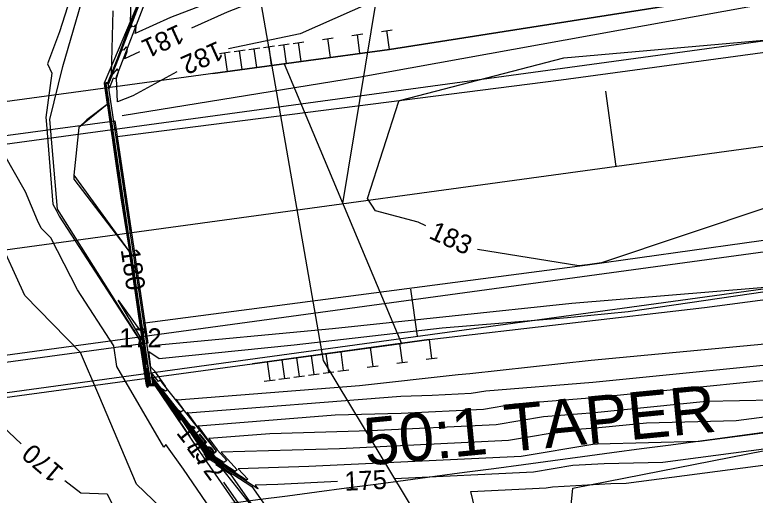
# Model space of a CAD drawing. Extents: x 2086416 to 2115205, y 575507 to 632762.
# Drawn here: x 2111556.7 to 2111634.6, y 581629.5 to 581680.1 of the extents above; entities that cross this region are included whole.
import ezdxf

# ---------------------------------------------------------------- set-up
doc = ezdxf.new("R2010")
doc.units = 0
for name, color, linetype in [('Default', 7, 'Continuous'), ('DTM Contours Major', 7, 'Continuous'), ('DTM Contours Major Text', 7, 'Continuous'), ('DTM Contours Minor', 7, 'Continuous'), ('DTM Contours Minor Text', 7, 'Continuous'), ('Exist Guardrail', 7, 'Continuous'), ('Exist Hydro Stream or Body of Water', 7, 'Continuous'), ('Exist Hydrographic Stream Bed', 7, 'Continuous'), ('Exist Right of Way Line', 7, 'Continuous'), ('Exist Roads EOP', 7, 'Continuous'), ('Exist Structure Major Bridge WW', 7, 'Continuous'), ('Exist Structure Major Deck Tunnel Box Culvert', 7, 'Continuous'), ('Exist Vegetation Woods Line', 7, 'Continuous'), ('Prop Horizontal Alignment', 7, 'Continuous'), ('Prop Horizontal Alignment Station Label', 7, 'Continuous'), ('Prop Horizontal Alignment Tick Large', 7, 'Continuous'), ('Prop Roadway Bridge', 7, 'Continuous'), ('Prop SS Cut Line', 7, 'Continuous')]:
    doc.layers.add(name, color=color, linetype=linetype)

msp = doc.modelspace()

# ---------------------------------------------------------------- linework, layer by layer
at = {"layer": 'Default'}
for p, q in [((2111430.061, 581649.328), (2112312.029, 581769.688)), ((2111433.036, 581627.53), (2112315.004, 581747.89)), ((2111508.232, 581633.802), (2112048.04, 581707.887)), ((2111629.262, 581649.262), (2111999.857, 581699.836)), ((2111629.262, 581649.262), (2111999.857, 581699.836)), ((2111596.112, 581676.446), (2111624.935, 581680.968)), ((2111624.935, 581680.968), (2111596.112, 581676.446)), ((2111595.274, 581678.35), (2111596.409, 581678.505)), ((2111596.112, 581676.446), (2111595.842, 581678.427)), ((2111589.081, 581677.505), (2111590.216, 581677.66)), ((2111592.178, 581677.927), (2111593.313, 581678.082)), ((2111593.016, 581676.023), (2111592.745, 581678.005)), ((2111584.437, 581676.871), (2111585.572, 581677.026)), ((2111585.275, 581674.967), (2111585.004, 581676.949)), ((2111585.985, 581677.082), (2111587.12, 581677.237)), ((2111586.823, 581675.178), (2111586.553, 581677.16)), ((2111589.919, 581675.601), (2111589.649, 581677.582)), ((2111577.534, 581673.911), (2111596.112, 581676.446)), ((2111596.112, 581676.446), (2111577.534, 581673.911)), ((2111578.244, 581676.026), (2111579.379, 581676.181)), ((2111579.082, 581674.122), (2111578.812, 581676.103)), ((2111579.793, 581676.237), (2111580.928, 581676.392)), ((2111580.63, 581674.333), (2111580.36, 581676.315)), ((2111581.341, 581676.449), (2111582.476, 581676.603)), ((2111582.179, 581674.544), (2111581.908, 581676.526)), ((2111582.889, 581676.66), (2111584.024, 581676.815)), ((2111583.727, 581674.756), (2111583.456, 581676.737)), ((2111599.054, 581646.267), (2111598.374, 581651.22)), ((2111600.281, 581645.896), (2111629.262, 581649.262)), ((2111600.281, 581645.896), (2111629.262, 581649.262)), ((2111581.703, 581643.36), (2111600.281, 581645.896)), ((2111600.281, 581645.896), (2111581.703, 581643.36)), ((2111600.281, 581645.896), (2111600.551, 581643.914)), ((2111594.088, 581645.051), (2111594.359, 581643.069)), ((2111597.185, 581645.473), (2111597.455, 581643.491)), ((2111587.896, 581644.205), (2111588.166, 581642.224)), ((2111589.444, 581644.417), (2111589.714, 581642.435)), ((2111590.992, 581644.628), (2111591.263, 581642.646)), ((2111583.251, 581643.572), (2111583.522, 581641.59)), ((2111584.8, 581643.783), (2111585.07, 581641.801)), ((2111586.348, 581643.994), (2111586.618, 581642.013)), ((2111596.888, 581643.414), (2111598.023, 581643.569)), ((2111599.984, 581643.837), (2111601.119, 581643.991)), ((2111590.695, 581642.569), (2111591.83, 581642.724)), ((2111593.791, 581642.992), (2111594.926, 581643.146)), ((2111584.502, 581641.724), (2111585.637, 581641.879)), ((2111586.051, 581641.935), (2111587.186, 581642.09)), ((2111587.599, 581642.146), (2111588.734, 581642.301)), ((2111589.147, 581642.358), (2111590.282, 581642.513)), ((2111582.954, 581641.513), (2111584.089, 581641.667))]:
    msp.add_line(p, q, dxfattribs=at)
at = {"layer": 'DTM Contours Major'}
for points in [[(2111577.062, 581633.567), (2111574.13, 581637.914), (2111571.386, 581641.335), (2111571.409, 581641.143), (2111571.336, 581641.132), (2111570.733, 581641.093), (2111570.186, 581644.597), (2111570.364, 581644.847), (2111569.098, 581653.407), (2111567.724, 581662.01), (2111566.227, 581672.465), (2111566.165, 581672.886), (2111566.466, 581672.935), (2111566.521, 581672.943), (2111566.528, 581672.934), (2111568.39, 581677.722), (2111570.775, 581684.171)], [(2111580.165, 581682.557), (2111573.082, 581679.801), (2111569.362, 581678.106), (2111569.457, 581678.372), (2111569.468, 581678.954), (2111569.404, 581679.039), (2111569.226, 581678.826), (2111569.08, 581678.891), (2111568.834, 581678.698), (2111566.565, 581672.861), (2111566.542, 581672.893), (2111566.359, 581672.866), (2111566.259, 581672.849), (2111566.467, 581671.443), (2111566.966, 581667.96), (2111567.423, 581665.095), (2111568.733, 581656.242)], [(2111563.624, 581644.535), (2111557.765, 581650.557), (2111554.83, 581656.943), (2111553.167, 581660.831), (2111550.584, 581662.207), (2111544.629, 581660.993), (2111538.463, 581666.005), (2111535.965, 581667.83), (2111530.949, 581672.288), (2111530.521, 581672.558), (2111527.53, 581672.834), (2111528.703, 581670.603), (2111528.883, 581668.916), (2111534.119, 581665.006), (2111537.381, 581653.906), (2111537.496, 581653.447), (2111544.432, 581648.303), (2111549.461, 581642.401), (2111557.401, 581634.942)], [(2111569.612, 581650.307), (2111570.775, 581642.449), (2111570.715, 581642.365), (2111570.897, 581641.201), (2111571.098, 581641.214), (2111571.287, 581641.242), (2111571.228, 581641.744)], [(2111571.228, 581641.744), (2111575.652, 581636.227), (2111575.847, 581636.099), (2111575.905, 581636.144), (2111576.193, 581636.349), (2111574.837, 581638.252), (2111574.911, 581638.195), (2111597.323, 581639.951), (2111600.607, 581640.048), (2111604.699, 581640.246), (2111606.241, 581640.505), (2111617.499, 581641.405), (2111642.062, 581643.861), (2111644.096, 581643.911), (2111647.513, 581644.36), (2111664.381, 581646.045)], [(2111561.972, 581631.067), (2111563.648, 581629.772), (2111566.428, 581629.67), (2111574.697, 581612.578), (2111574.966, 581612.195), (2111584.328, 581609.029), (2111586.691, 581607.388), (2111582.492, 581616.152), (2111576.474, 581624.007), (2111569.516, 581630.68), (2111565.57, 581640.043), (2111563.624, 581644.535)], [(2111696.049, 581641.363), (2111672.077, 581638.811), (2111669.843, 581638.828), (2111651.777, 581636.424), (2111648.999, 581636.147), (2111624.869, 581632.976), (2111618.681, 581632.825), (2111615.387, 581632.634), (2111611.27, 581631.941), (2111596.647, 581631.235)], [(2111590.654, 581630.945), (2111584.392, 581630.643), (2111581.999, 581630.572), (2111582.326, 581630.219), (2111582.283, 581630.187), (2111577.062, 581633.567)]]:
    msp.add_lwpolyline(points, dxfattribs=at)
at = {"layer": 'DTM Contours Minor'}
for points in [[(2111554.563, 581717.65), (2111557.36, 581715.394), (2111558.77, 581713.514), (2111570.458, 581698.119), (2111560.752, 581706.535), (2111561.783, 581697.351), (2111565.987, 581692.592), (2111561.42, 581678.299), (2111560.172, 581674.931), (2111560.629, 581673.945), (2111559.995, 581669.266), (2111560.03, 581668.962), (2111560.707, 581660.161), (2111561.06, 581659.542), (2111561.396, 581658.891), (2111569.796, 581645.905), (2111570.547, 581641.087), (2111570.686, 581640.847), (2111570.828, 581641.041), (2111571.479, 581641.083), (2111571.482, 581641.083), (2111571.481, 581641.089), (2111571.569, 581640.98), (2111575.135, 581635.693)], [(2111771.48, 581708.935), (2111760.551, 581707.387), (2111751.324, 581706.065), (2111741.049, 581703.184), (2111726.364, 581703.031), (2111711.255, 581700.898), (2111699.308, 581700.058), (2111691.644, 581698.037), (2111679.979, 581697.458), (2111663.055, 581697.517), (2111661.641, 581697.308), (2111661.538, 581697.284), (2111642.179, 581694.795), (2111641.925, 581694.737), (2111612.432, 581690.93), (2111612.349, 581690.915), (2111598.441, 581688.663), (2111596.352, 581688.299), (2111593.432, 581686.787), (2111582.067, 581681.437), (2111581.765, 581681.432), (2111579.054, 581680.377), (2111575.311, 581678.672)], [(2111775.952, 581702.182), (2111765.879, 581701.692), (2111760.907, 581700.977), (2111757.858, 581700.672), (2111741.952, 581696.212), (2111712.843, 581695.908), (2111712.055, 581695.797), (2111711.432, 581695.753), (2111692.466, 581690.751), (2111663.596, 581689.317), (2111662.082, 581689.322), (2111660.385, 581689.117), (2111642.993, 581686.483), (2111626.562, 581686.502), (2111613.936, 581684.954), (2111604.265, 581685.115), (2111597.651, 581682.972), (2111586.742, 581678.077), (2111579.19, 581676.523)], [(2111569.01, 581685.022), (2111568.855, 581679.129), (2111567.524, 581675.529), (2111566.521, 581672.948), (2111566.517, 581672.953), (2111566.487, 581672.949), (2111566.146, 581672.893), (2111566.179, 581672.67), (2111567.876, 581660.82), (2111569.433, 581651.069), (2111570.282, 581645.327), (2111570.08, 581645.043), (2111570.701, 581641.072), (2111571.384, 581641.115), (2111571.433, 581641.123), (2111571.418, 581641.253), (2111573.276, 581638.936), (2111576.945, 581633.496), (2111581.656, 581630.446), (2111583.793, 581627.386), (2111584.244, 581626.917), (2111585.478, 581625.384)], [(2111577.178, 581633.638), (2111574.983, 581636.892), (2111571.354, 581641.416), (2111571.385, 581641.163), (2111571.288, 581641.148), (2111570.766, 581641.115), (2111570.292, 581644.15), (2111570.446, 581644.368), (2111568.763, 581655.744), (2111567.573, 581663.2), (2111566.275, 581672.261), (2111566.184, 581672.878), (2111566.444, 581672.921), (2111566.525, 581672.933), (2111566.535, 581672.919), (2111569.255, 581679.915), (2111570.799, 581684.09)], [(2111577.411, 581633.781), (2111576.691, 581634.848), (2111571.291, 581641.58), (2111571.336, 581641.203), (2111571.193, 581641.181), (2111570.832, 581641.158), (2111570.504, 581643.258), (2111570.611, 581643.408), (2111568.093, 581660.42), (2111567.269, 581665.58), (2111566.371, 581671.852), (2111566.221, 581672.864), (2111566.402, 581672.893), (2111566.534, 581672.913), (2111566.55, 581672.89), (2111570.691, 581683.54)], [(2111576.272, 581682.839), (2111573.71, 581682.421), (2111570.375, 581681.023), (2111570.381, 581681.335), (2111570.364, 581681.358), (2111570.316, 581681.3), (2111570.109, 581681.392), (2111569.763, 581681.119), (2111566.558, 581672.876), (2111566.538, 581672.903), (2111566.381, 581672.879), (2111566.24, 581672.856), (2111566.419, 581671.647), (2111567.118, 581666.77), (2111567.758, 581662.757), (2111570.693, 581642.928), (2111570.61, 581642.812), (2111570.865, 581641.18), (2111571.145, 581641.198), (2111571.312, 581641.222), (2111571.26, 581641.662)], [(2111577.294, 581633.709), (2111575.837, 581635.87), (2111571.323, 581641.498), (2111571.36, 581641.183), (2111571.241, 581641.165), (2111570.799, 581641.136), (2111570.398, 581643.704), (2111570.529, 581643.888), (2111568.428, 581658.082), (2111567.421, 581664.39), (2111566.323, 581672.056), (2111566.203, 581672.871), (2111566.423, 581672.907), (2111566.53, 581672.923), (2111566.543, 581672.905), (2111570.121, 581682.109)], [(2111567.025, 581680.498), (2111566.851, 581673.856), (2111566.658, 581673.336), (2111566.513, 581672.963), (2111566.513, 581672.963), (2111566.508, 581672.963), (2111566.127, 581672.9), (2111566.131, 581672.874), (2111566.449, 581670.656), (2111564.307, 581669.018), (2111563.443, 581668.224), (2111562.943, 581663.213), (2111562.927, 581662.803), (2111568.739, 581655.173), (2111569.767, 581648.731), (2111570.2, 581645.807), (2111569.974, 581645.489), (2111570.668, 581641.05), (2111571.432, 581641.099), (2111571.457, 581641.103), (2111571.449, 581641.171), (2111572.422, 581639.958), (2111574.154, 581637.391)], [(2111643.847, 581677.764), (2111644.952, 581677.932), (2111662.194, 581679.764), (2111662.971, 581679.587), (2111663.56, 581679.562), (2111683.069, 581679.032), (2111693.952, 581679.325), (2111701.93, 581679.257), (2111713.811, 581679.697), (2111722.926, 581678.431), (2111717.299, 581676.654), (2111714.292, 581675.929), (2111711.547, 581675.446), (2111695.04, 581672.327), (2111687.453, 581670.987), (2111665.531, 581666.866), (2111655.863, 581664.226), (2111646.097, 581662.087), (2111636.124, 581659.903), (2111618.397, 581653.989), (2111616.941, 581653.759), (2111616.037, 581653.667), (2111605.38, 581655.386)], [(2111599.933, 581657.871), (2111599.142, 581658.247), (2111594.644, 581659.471), (2111593.813, 581660.769), (2111597.108, 581671.011), (2111597.122, 581671.059), (2111597.229, 581671.081), (2111597.239, 581671.086), (2111597.297, 581671.105), (2111614.462, 581675.567), (2111639.449, 581677.769), (2111643.847, 581677.764)], [(2111569.851, 581676.185), (2111568.274, 581675.467), (2111568.549, 581676.238), (2111568.556, 581676.573), (2111568.444, 581676.72), (2111568.136, 581676.352), (2111568.05, 581676.39), (2111567.906, 581676.276), (2111566.572, 581672.847), (2111566.547, 581672.883), (2111566.338, 581672.852), (2111566.278, 581672.842), (2111566.515, 581671.238), (2111566.814, 581669.15), (2111567.088, 581667.433), (2111570.857, 581641.969), (2111570.821, 581641.919), (2111570.93, 581641.223), (2111571.05, 581641.231), (2111571.263, 581641.262), (2111571.196, 581641.825)], [(2111573.759, 581674.096), (2111569.118, 581671.56), (2111567.528, 581670.942), (2111567.402, 581673.431), (2111567.641, 581674.104), (2111567.643, 581674.192), (2111567.484, 581674.402), (2111567.046, 581673.878), (2111567.021, 581673.889), (2111566.978, 581673.855), (2111566.58, 581672.832), (2111566.551, 581672.873), (2111566.317, 581672.838), (2111566.297, 581672.835), (2111566.563, 581671.034), (2111566.662, 581670.341), (2111566.753, 581669.77), (2111570.939, 581641.489), (2111570.927, 581641.473), (2111570.963, 581641.244), (2111571.002, 581641.247), (2111571.239, 581641.282), (2111571.165, 581641.907)], [(2111598.535, 581596.664), (2111585.912, 581617.09), (2111584.535, 581618.974), (2111576.895, 581628.719), (2111574.477, 581632.249), (2111572.617, 581634.865), (2111572.402, 581634.572), (2111567.467, 581643.071), (2111567.127, 581645.256), (2111563.317, 581651.146), (2111560.505, 581656.601), (2111559.492, 581657.643), (2111559.123, 581658.446), (2111557.832, 581661.464), (2111555.517, 581665.512)], [(2111571.165, 581641.907), (2111571.996, 581640.87), (2111572.571, 581640.492), (2111572.743, 581640.626), (2111572.795, 581640.663), (2111572.546, 581641.013), (2111572.584, 581640.984), (2111571.455, 581642.576), (2111571.032, 581643.012), (2111570.823, 581644.648), (2111571.916, 581643.904), (2111586.094, 581645.355), (2111601.664, 581647.121), (2111614.846, 581648.211), (2111616.947, 581648.442), (2111621.236, 581648.843), (2111646.92, 581652.625), (2111665.944, 581653.445), (2111667.701, 581653.608), (2111692.097, 581649.43)], [(2111569.975, 581646.085), (2111567.608, 581650.059), (2111569.849, 581646.913), (2111570.065, 581646.63), (2111570.102, 581646.394), (2111570.118, 581646.287), (2111569.975, 581646.085)], [(2111571.196, 581641.825), (2111573.824, 581638.549), (2111574.209, 581638.295), (2111574.324, 581638.385), (2111574.494, 581638.506), (2111573.692, 581639.632), (2111573.792, 581639.556), (2111592.953, 581641.057), (2111603.347, 581642.235), (2111604.567, 581642.336), (2111617.335, 581643.741), (2111643.391, 581646.181), (2111647.216, 581646.744), (2111650.05, 581646.866), (2111668.074, 581648.539), (2111670.919, 581648.052), (2111693.464, 581647.881)], [(2111571.26, 581641.662), (2111577.48, 581633.906), (2111577.485, 581633.903), (2111577.486, 581633.904), (2111577.892, 581634.191), (2111575.982, 581636.871), (2111576.03, 581636.835), (2111590.423, 581637.963), (2111597.364, 581638.167), (2111606.013, 581638.585), (2111609.271, 581639.133), (2111617.594, 581639.798), (2111635.752, 581641.614), (2111640.25, 581641.724), (2111647.81, 581642.717), (2111662.919, 581644.226), (2111668.671, 581644.992), (2111686.335, 581644.858)], [(2111671.884, 581640.351), (2111669.55, 581640.369), (2111654.563, 581638.375), (2111648.702, 581637.79), (2111628.715, 581635.163), (2111617.979, 581634.901), (2111617.512, 581634.874), (2111609.956, 581633.602), (2111587.635, 581632.524), (2111580.203, 581632.305), (2111581.22, 581631.207), (2111581.086, 581631.108), (2111577.178, 581633.638)], [(2111638.154, 581639.767), (2111636.405, 581639.537), (2111629.442, 581639.367), (2111617.689, 581638.192), (2111612.302, 581637.761), (2111607.327, 581636.924), (2111594.121, 581636.286), (2111583.523, 581635.974), (2111577.149, 581635.474), (2111577.128, 581635.491), (2111577.984, 581634.288), (2111579.007, 581633.185), (2111578.692, 581632.951), (2111577.411, 581633.781)], [(2111655.217, 581640.113), (2111648.405, 581639.432), (2111632.56, 581637.35), (2111623.132, 581637.12), (2111617.784, 581636.585), (2111615.332, 581636.39), (2111608.642, 581635.263), (2111590.878, 581634.405), (2111578.406, 581634.038), (2111580.113, 581632.196), (2111579.889, 581632.029), (2111577.294, 581633.709)], [(2111589.242, 581620.711), (2111589.877, 581619.921), (2111590.857, 581618.927), (2111592.405, 581618.486), (2111599.33, 581615.104), (2111605.372, 581623.887), (2111605.711, 581625.528), (2111604.66, 581629.897), (2111612.584, 581630.28), (2111613.262, 581630.394), (2111619.383, 581630.749), (2111621.024, 581630.789), (2111642.89, 581633.662), (2111647.196, 581633.15), (2111648.463, 581631.541), (2111653.203, 581633.039), (2111670.864, 581631.971), (2111682.196, 581631.349), (2111685.064, 581615.457), (2111702.133, 581615.465), (2111706.656, 581602.934), (2111726.967, 581593.524), (2111719.652, 581583.63), (2111725.706, 581574.006)], [(2111577.85, 581632.764), (2111579.379, 581631.774), (2111585.586, 581622.885), (2111586.895, 581621.522), (2111588.77, 581619.193), (2111592.833, 581615.071), (2111599.247, 581613.245), (2111610.211, 581607.891), (2111612.256, 581606.571), (2111617.699, 581603.706), (2111619.118, 581601.942), (2111619.518, 581603.35), (2111619.215, 581603.582), (2111621.458, 581611.664), (2111622.113, 581614.012), (2111639.991, 581603.538), (2111640.806, 581603.356), (2111642.077, 581602.394), (2111666.164, 581595.53), (2111674.849, 581575.034)], [(2111578.656, 581630.876), (2111587.378, 581618.383), (2111587.912, 581617.828), (2111588.893, 581616.777), (2111596.136, 581605.984), (2111600.862, 581598.818)]]:
    msp.add_lwpolyline(points, dxfattribs=at)
at = {"layer": 'Exist Guardrail'}
for points in [[(2111568.013, 581669.491), (2111592.858, 581673.514), (2111642.147, 581682.489), (2111666.782, 581686.916), (2111710.045, 581692.984), (2111759.576, 581699.833), (2111809.182, 581706.828), (2111858.616, 581713.631), (2111908.173, 581720.547), (2111932.899, 581724.161), (2111951.42, 581726.236), (2112007.614, 581731.068), (2112026.509, 581732.213), (2112051.896, 581735.258)], [(2112054.856, 581711.069), (2112029.646, 581707.045), (2112011.617, 581703.659), (2111962.454, 581694.474), (2111912.649, 581687.28), (2111863.136, 581680.434), (2111788.924, 581671.299), (2111764.18, 581666.791), (2111714.584, 581659.947), (2111683.609, 581655.725), (2111671.135, 581654.366), (2111664.873, 581653.791), (2111615.307, 581649.71), (2111590.13, 581647.036), (2111571.455, 581645.262)]]:
    msp.add_lwpolyline(points, dxfattribs=at)
at = {"layer": 'Exist Hydro Stream or Body of Water'}
msp.add_lwpolyline([(2111621.041, 581592.195), (2111611.64, 581604.325), (2111605.912, 581608.14), (2111600.475, 581607.014), (2111602.119, 581600.097), (2111601.107, 581599.205), (2111587.776, 581617.384), (2111576.692, 581633.341), (2111571.484, 581641.081), (2111570.636, 581641.029), (2111569.871, 581645.923), (2111561.21, 581659.642), (2111560.398, 581669.08), (2111561.77, 581674.655), (2111567.139, 581693.151), (2111571.775, 581696.534), (2111557.095, 581714.198), (2111551.353, 581722.025)], dxfattribs=at)
at = {"layer": 'Exist Hydrographic Stream Bed'}
msp.add_lwpolyline([(2112129.652, 582477.712), (2111835.899, 582368.961), (2111727.147, 582231.15), (2111672.647, 582129.589), (2111610.896, 582009.957), (2111585.646, 581897.526), (2111574.646, 581806.895), (2111574.646, 581727.084), (2111582.896, 581679.524), (2111589.146, 581643.704), (2111621.896, 581589.333), (2111665.397, 581516.772), (2111701.647, 581379.011), (2111737.898, 581248.45), (2111785.148, 581103.388)], dxfattribs=at)
at = {"layer": 'Exist Right of Way Line'}
msp.add_arc((2108326.546, 606231.499), 24816.937, 277.3939111, 277.8562149, dxfattribs=at)
at = {"layer": 'Exist Roads EOP'}
for points in [[(2111568.946, 581657.382), (2111567.482, 581667.278), (2111614.169, 581673.234), (2111663.501, 581679.942), (2111712.967, 581686.457), (2111762.009, 581693.34), (2111810.989, 581700.16), (2111860.082, 581706.99), (2111909.436, 581713.775), (2111958.293, 581720.29), (2112007.473, 581726.809), (2112052.556, 581733.019), (2112053.866, 581723.651)], [(2111568.946, 581657.382), (2111567.482, 581667.278), (2111614.169, 581673.234), (2111663.501, 581679.942), (2111712.967, 581686.457), (2111762.009, 581693.34), (2111810.989, 581700.16), (2111860.082, 581706.99), (2111909.436, 581713.775), (2111958.293, 581720.29), (2112007.473, 581726.809), (2112052.556, 581733.019), (2112053.866, 581723.651)], [(2111568.946, 581657.382), (2111570.384, 581647.665), (2111616.941, 581653.786), (2111666.479, 581660.703), (2111715.395, 581667.634), (2111764.576, 581674.503), (2111813.386, 581681.192), (2111862.599, 581687.866), (2111911.635, 581694.622), (2111960.562, 581701.229), (2112009.92, 581707.698), (2112055.279, 581713.547), (2112053.866, 581723.651)]]:
    msp.add_lwpolyline(points, dxfattribs=at)
at = {"layer": 'Exist Structure Major Bridge WW'}
for points in [[(2111566.583, 581672.826), (2111566.849, 581673.52), (2111570.25, 581682.39), (2111570.844, 581683.94), (2111571.077, 581683.851), (2111570.483, 581682.3), (2111570.717, 581682.211), (2111567.316, 581673.341), (2111567.082, 581673.43), (2111566.658, 581672.322), (2111566.583, 581672.826)], [(2111566.553, 581672.868), (2111566.306, 581672.831), (2111570.979, 581641.255), (2111571.227, 581641.292), (2111566.553, 581672.868)], [(2111571.15, 581641.945), (2111571.908, 581640.981), (2111577.524, 581633.85), (2111577.917, 581634.159), (2111572.301, 581641.291), (2111572.031, 581641.634), (2111571.834, 581641.48), (2111571.075, 581642.444), (2111571.15, 581641.945)]]:
    msp.add_lwpolyline(points, dxfattribs=at)
at = {"layer": 'Exist Structure Major Deck Tunnel Box Culvert'}
msp.add_lwpolyline([(2111518.338, 581638.473), (2111518.005, 581640.729), (2111516.542, 581650.631), (2111515.092, 581660.442), (2111514.879, 581661.883), (2111532.718, 581664.281), (2111549.455, 581666.531), (2111567.238, 581668.922), (2111567.482, 581667.278), (2111568.946, 581657.382), (2111570.384, 581647.665), (2111570.703, 581645.511), (2111552.911, 581643.12), (2111536.107, 581640.862), (2111518.338, 581638.473)], dxfattribs=at)
at = {"layer": 'Exist Vegetation Woods Line'}
msp.add_lwpolyline([(2111779.567, 581491.973), (2111763.785, 581504.851), (2111745.339, 581525.059), (2111717.304, 581555.588), (2111690.346, 581575.953), (2111665.09, 581587.143), (2111644.347, 581594.336), (2111622.456, 581605.396), (2111614.175, 581617.919), (2111615.41, 581630.255), (2111644.692, 581636.018), (2111711.675, 581643.899), (2111763.228, 581655.57), (2111785.51, 581656)], dxfattribs=at)
at = {"layer": 'Prop Horizontal Alignment'}
msp.add_line((2111431.548, 581638.429), (2112404.465, 581771.2), dxfattribs=at)
at = {"layer": 'Prop Horizontal Alignment Station Label'}
msp.add_line((2111591.211, 581660.217), (2111612.471, 581789.237), dxfattribs=at)
at = {"layer": 'Prop Horizontal Alignment Tick Large'}
msp.add_line((2111619.945, 581664.139), (2111618.863, 581672.065), dxfattribs=at)
at = {"layer": 'Prop Roadway Bridge'}
for p, q in [((2111585.034, 581674.934), (2111495.86, 581662.765)), ((2111585.034, 581674.934), (2111597.389, 581645.501)), ((2111508.215, 581633.332), (2111597.389, 581645.501))]:
    msp.add_line(p, q, dxfattribs=at)
at = {"layer": 'Prop SS Cut Line'}
for p, q in [((2111570.02, 581682.16), (2111566.127, 581672.9)), ((2111566.127, 581672.9), (2111566.449, 581670.656)), ((2111566.449, 581670.656), (2111563.443, 581668.224)), ((2111563.443, 581668.224), (2111562.943, 581663.213)), ((2111562.943, 581663.213), (2111568.739, 581655.173)), ((2111568.739, 581655.173), (2111570.766, 581641.115)), ((2111570.766, 581641.115), (2111571.503, 581641.14)), ((2111571.503, 581641.14), (2111582.793, 581626.876))]:
    msp.add_line(p, q, dxfattribs=at)

# ---------------------------------------------------------------- texts
at = {"layer": 'Default'}
msp.add_text('50:1 TAPER', height=5, rotation=5.54573, dxfattribs=at).set_placement((2111593.639, 581632.62))
at = {"layer": 'DTM Contours Major Text'}
for s, rotation, p in [('180', 278.41848, (2111567.85, 581655.379)), ('170', 139.71038, (2111561.981, 581632.192)), ('175', 2.76607, (2111591.426, 581629.981))]:
    msp.add_text(s, height=2, rotation=rotation, dxfattribs=at).set_placement(p)
at = {"layer": 'DTM Contours Minor Text'}
for s, rotation, p in [('181', 204.48892, (2111573.929, 581679.142)), ('182', 204.08493, (2111578.062, 581677.376)), ('183', 335.47756, (2111600.157, 581656.617)), ('173', 308.61859, (2111573.63, 581636.058)), ('172', 306.16573, (2111574.713, 581634.504))]:
    msp.add_text(s, height=2, rotation=rotation, dxfattribs=at).set_placement(p)
msp.add_text('172', height=2, dxfattribs=at).set_placement((2111567.699, 581645.085))

doc.saveas('drawing.dxf')
